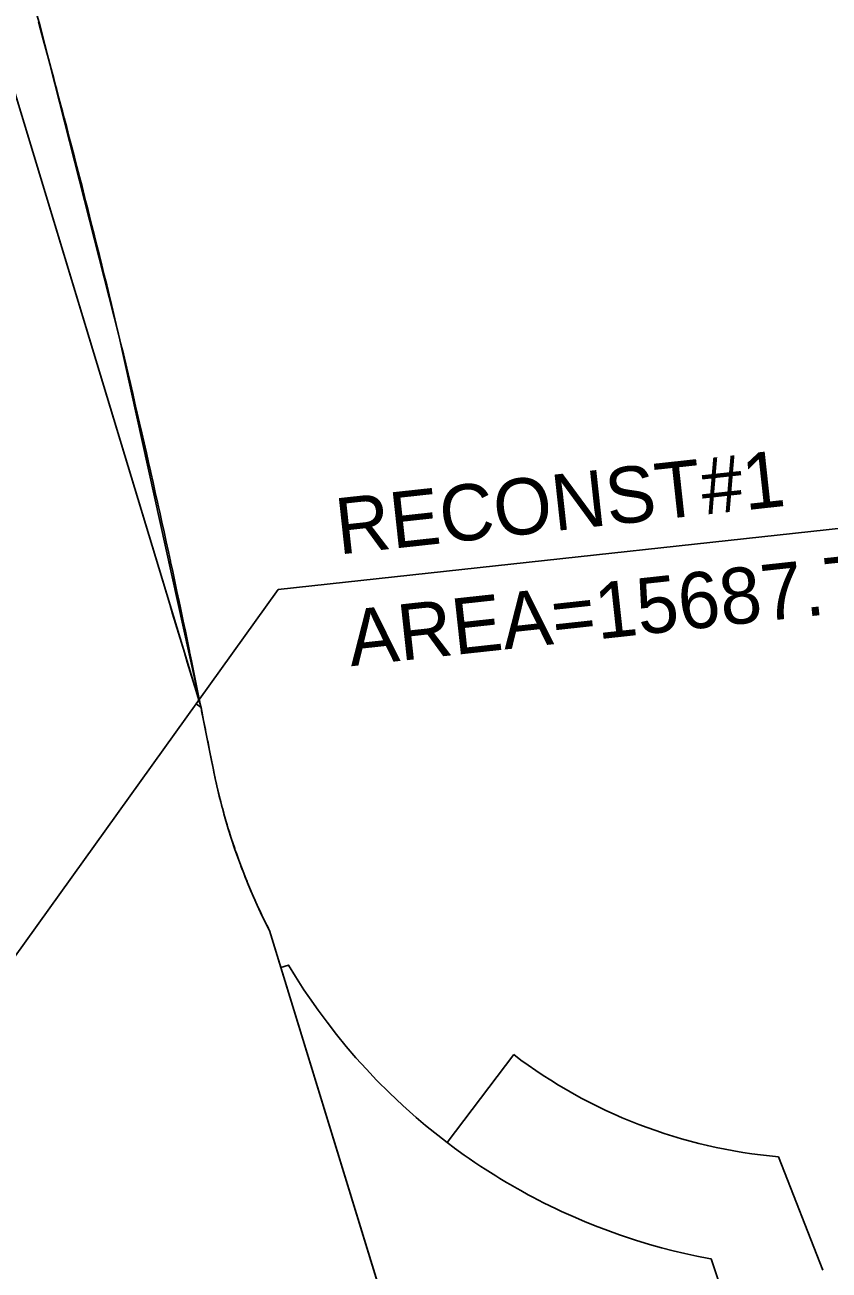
# Model space of a CAD drawing. Extents: x 1509538 to 1510847, y 401283 to 402022.
# Drawn here: x 1509788.8 to 1509828.9, y 401687.8 to 401749.8 of the extents above; entities that cross this region are included whole.
import ezdxf

# ---------------------------------------------------------------- set-up
doc = ezdxf.new("R2010")
doc.units = 0
for name, color, linetype in [('LAWE_P_T', 7, 'Continuous'), ('Level 2', 7, 'Continuous'), ('Level 3', 7, 'Continuous'), ('Level 5', 7, 'Continuous'), ('Level 8', 7, 'Continuous')]:
    doc.layers.add(name, color=color, linetype=linetype)

msp = doc.modelspace()

# ---------------------------------------------------------------- linework, layer by layer
at = {"layer": 'LAWE_P_T'}
msp.add_lwpolyline([(1509787.163, 401701.771), (1509801.464, 401721.693), (1509837.165, 401725.585)], dxfattribs=at)
at = {"layer": 'Level 2'}
for p, q in [((1509796.641, 401719.03), (1509796.494, 401719.512)), ((1509797.079, 401717.584), (1509796.933, 401718.066)), ((1509797.225, 401717.102), (1509797.079, 401717.584)), ((1509797.368, 401715.987), (1509797.505, 401716.178)), ((1509812.832, 401666.242), (1509801.026, 401704.701)), ((1509801.593, 401702.854), (1509801.026, 401704.701)), ((1509812.832, 401666.242), (1509801.593, 401702.854))]:
    msp.add_line(p, q, dxfattribs=at)
for points in [[(1509797.617, 401715.809), (1509783.046, 401763.871), (1509766.293, 401811.158), (1509745.325, 401858.521), (1509715.312, 401901.724)], [(1509796.056, 401720.959), (1509783.046, 401763.871), (1509766.293, 401811.158), (1509745.325, 401858.521)], [(1509796.494, 401719.512), (1509796.348, 401719.994), (1509796.202, 401720.476), (1509796.056, 401720.959)], [(1509796.933, 401718.066), (1509796.787, 401718.548), (1509796.641, 401719.03)], [(1509797.505, 401716.178), (1509797.371, 401716.621), (1509797.225, 401717.102)], [(1509797.617, 401715.809), (1509797.368, 401715.987)], [(1509801.026, 401704.701), (1509800.978, 401704.795), (1509800.94, 401704.87), (1509800.854, 401705.041), (1509800.804, 401705.142), (1509800.672, 401705.414), (1509800.652, 401705.457), (1509800.542, 401705.688), (1509800.509, 401705.759), (1509800.456, 401705.875), (1509800.415, 401705.964), (1509800.351, 401706.105), (1509800.291, 401706.24), (1509800.267, 401706.293), (1509800.169, 401706.518), (1509800.123, 401706.624), (1509800.086, 401706.713), (1509800.075, 401706.738), (1509800.05, 401706.797), (1509799.934, 401707.077), (1509799.911, 401707.133), (1509799.82, 401707.358), (1509799.743, 401707.555), (1509799.71, 401707.64), (1509799.674, 401707.732), (1509799.602, 401707.923), (1509799.581, 401707.978), (1509799.497, 401708.208), (1509799.427, 401708.402), (1509799.394, 401708.493), (1509799.308, 401708.739), (1509799.295, 401708.779), (1509799.279, 401708.826), (1509799.198, 401709.067), (1509799.137, 401709.252), (1509799.104, 401709.355), (1509799.013, 401709.644), (1509799.002, 401709.679), (1509798.977, 401709.758), (1509798.924, 401709.934), (1509798.914, 401709.969), (1509798.873, 401710.108), (1509798.839, 401710.225), (1509798.756, 401710.516), (1509798.751, 401710.537), (1509798.682, 401710.788), (1509798.677, 401710.809), (1509798.638, 401710.956), (1509798.635, 401710.967), (1509798.6, 401711.102), (1509798.526, 401711.396), (1509798.525, 401711.399), (1509798.454, 401711.691), (1509798.422, 401711.828), (1509798.422, 401711.831), (1509798.386, 401711.986), (1509798.324, 401712.265), (1509798.321, 401712.282), (1509798.258, 401712.579), (1509798.234, 401712.7), (1509798.199, 401712.876), (1509798.141, 401713.172), (1509798.043, 401713.669), (1509797.965, 401714.066), (1509797.945, 401714.165), (1509797.847, 401714.661), (1509797.835, 401714.721), (1509797.748, 401715.157), (1509797.648, 401715.652), (1509797.633, 401715.731), (1509797.617, 401715.809)], [(1509801.026, 401704.701), (1509800.672, 401705.414), (1509800.415, 401705.964), (1509800.169, 401706.518), (1509799.934, 401707.077), (1509799.71, 401707.64), (1509799.497, 401708.208), (1509799.308, 401708.739), (1509799.137, 401709.252), (1509798.977, 401709.758), (1509798.756, 401710.516), (1509798.6, 401711.102), (1509798.454, 401711.691), (1509798.324, 401712.265), (1509798.199, 401712.876), (1509798.043, 401713.669), (1509797.945, 401714.165), (1509797.847, 401714.661), (1509797.748, 401715.157), (1509797.617, 401715.809)]]:
    msp.add_lwpolyline(points, dxfattribs=at)
at = {"layer": 'Level 3'}
msp.add_line((1509797.617, 401715.809), (1509797.548, 401716.148), dxfattribs=at)
for points in [[(1509715.312, 401901.724), (1509745.325, 401858.521), (1509766.293, 401811.158), (1509783.046, 401763.871), (1509797.617, 401715.809)], [(1509797.548, 401716.148), (1509797.448, 401716.644), (1509797.347, 401717.139), (1509797.246, 401717.635), (1509797.144, 401718.13), (1509797.049, 401718.588), (1509797.041, 401718.625), (1509796.939, 401719.12), (1509796.835, 401719.615), (1509796.731, 401720.11), (1509796.627, 401720.605), (1509796.591, 401720.774), (1509796.522, 401721.1), (1509796.417, 401721.594), (1509796.311, 401722.089), (1509796.205, 401722.583), (1509796.098, 401723.078), (1509796.093, 401723.102), (1509795.991, 401723.572), (1509795.883, 401724.066), (1509795.775, 401724.56), (1509795.666, 401725.054), (1509795.557, 401725.547), (1509795.5, 401725.807), (1509795.448, 401726.041), (1509795.338, 401726.535), (1509795.227, 401727.028), (1509795.116, 401727.521), (1509795.097, 401727.607), (1509795.004, 401728.015), (1509794.892, 401728.508), (1509794.78, 401729.001), (1509794.667, 401729.494), (1509794.553, 401729.986), (1509794.439, 401730.479), (1509794.358, 401730.829), (1509794.325, 401730.972), (1509794.21, 401731.464), (1509794.094, 401731.956), (1509794.06, 401732.103), (1509793.978, 401732.449), (1509793.862, 401732.941), (1509793.745, 401733.433), (1509793.627, 401733.925), (1509793.51, 401734.416), (1509793.391, 401734.908), (1509793.272, 401735.399), (1509793.166, 401735.839), (1509793.153, 401735.891), (1509793.033, 401736.382), (1509792.983, 401736.589), (1509792.913, 401736.873), (1509792.792, 401737.364), (1509792.671, 401737.855), (1509792.549, 401738.346), (1509792.427, 401738.837), (1509792.304, 401739.327), (1509792.181, 401739.818), (1509792.057, 401740.308), (1509791.933, 401740.798), (1509791.924, 401740.837), (1509791.865, 401741.066), (1509791.809, 401741.288), (1509791.684, 401741.778), (1509791.558, 401742.268), (1509791.432, 401742.758), (1509791.305, 401743.248), (1509791.178, 401743.737), (1509791.051, 401744.226), (1509790.923, 401744.716), (1509790.794, 401745.205), (1509790.708, 401745.533), (1509790.666, 401745.694), (1509790.631, 401745.822), (1509790.536, 401746.183), (1509790.406, 401746.671), (1509790.367, 401746.818), (1509790.276, 401747.16), (1509790.145, 401747.648), (1509790.014, 401748.137), (1509789.882, 401748.625), (1509789.749, 401749.113), (1509789.617, 401749.601), (1509789.511, 401749.989)], [(1509812.832, 401666.242), (1509801.593, 401702.854), (1509801.98, 401702.973), (1509802.329, 401702.401), (1509802.75, 401701.745), (1509803.023, 401701.338), (1509803.452, 401700.727), (1509803.897, 401700.123), (1509804.366, 401699.518), (1509804.857, 401698.917), (1509805.338, 401698.356), (1509805.858, 401697.779), (1509806.366, 401697.242), (1509807.009, 401696.598), (1509807.67, 401695.974), (1509808.349, 401695.369), (1509808.808, 401694.98), (1509809.89, 401694.121), (1509810.241, 401693.858), (1509810.244, 401693.856), (1509810.248, 401693.853), (1509810.736, 401693.502), (1509810.985, 401693.33), (1509811.262, 401693.138), (1509811.563, 401692.939), (1509811.781, 401692.795), (1509812.307, 401692.462), (1509812.51, 401692.339), (1509812.84, 401692.139), (1509813.033, 401692.028), (1509813.379, 401691.828), (1509813.56, 401691.728), (1509813.924, 401691.527), (1509814.092, 401691.439), (1509814.475, 401691.237), (1509814.663, 401691.143), (1509815.032, 401690.958), (1509815.295, 401690.833), (1509815.595, 401690.691), (1509816.162, 401690.435), (1509816.735, 401690.191), (1509817.258, 401689.979), (1509817.894, 401689.736), (1509818.481, 401689.526), (1509819.071, 401689.329), (1509819.28, 401689.265), (1509819.98, 401689.05), (1509820.564, 401688.886), (1509821.151, 401688.734), (1509821.74, 401688.594), (1509822.333, 401688.465), (1509822.928, 401688.348), (1509823.042, 401688.328), (1509823.042, 401688.327), (1509828.278, 401672.51)]]:
    msp.add_lwpolyline(points, dxfattribs=at)
at = {"layer": 'Level 5'}
for p, q in [((1509789.583, 401749.833), (1509783.259, 401771.222)), ((1509793.533, 401734.281), (1509789.583, 401749.833)), ((1509797.622, 401715.782), (1509793.533, 401734.281)), ((1509801.026, 401704.701), (1509801.593, 401702.854)), ((1509801.593, 401702.854), (1509801.026, 401704.701)), ((1509801.593, 401702.854), (1509801.98, 401702.973)), ((1509801.98, 401702.973), (1509801.593, 401702.854)), ((1509801.98, 401702.973), (1509802.329, 401702.401)), ((1509802.329, 401702.401), (1509801.98, 401702.973)), ((1509802.329, 401702.401), (1509802.75, 401701.745)), ((1509802.75, 401701.745), (1509802.329, 401702.401)), ((1509802.75, 401701.745), (1509803.023, 401701.338)), ((1509803.023, 401701.338), (1509802.75, 401701.745)), ((1509803.023, 401701.338), (1509803.452, 401700.727)), ((1509803.452, 401700.727), (1509803.023, 401701.338)), ((1509803.452, 401700.727), (1509803.897, 401700.123)), ((1509803.897, 401700.123), (1509803.452, 401700.727)), ((1509803.897, 401700.123), (1509804.366, 401699.518)), ((1509804.366, 401699.518), (1509803.897, 401700.123)), ((1509804.366, 401699.518), (1509804.857, 401698.917)), ((1509804.857, 401698.917), (1509804.366, 401699.518)), ((1509804.857, 401698.917), (1509805.338, 401698.356)), ((1509805.338, 401698.356), (1509804.857, 401698.917)), ((1509805.338, 401698.356), (1509805.858, 401697.779)), ((1509805.858, 401697.779), (1509805.338, 401698.356)), ((1509813.205, 401698.509), (1509809.88, 401694.129)), ((1509805.858, 401697.779), (1509806.366, 401697.242)), ((1509806.366, 401697.242), (1509805.858, 401697.779)), ((1509806.366, 401697.242), (1509807.009, 401696.598)), ((1509807.009, 401696.598), (1509806.366, 401697.242)), ((1509807.009, 401696.598), (1509807.67, 401695.974)), ((1509807.67, 401695.974), (1509807.009, 401696.598)), ((1509807.67, 401695.974), (1509808.349, 401695.369)), ((1509808.349, 401695.369), (1509807.67, 401695.974)), ((1509808.349, 401695.369), (1509808.808, 401694.98)), ((1509808.808, 401694.98), (1509808.349, 401695.369)), ((1509808.808, 401694.98), (1509809.88, 401694.129)), ((1509809.88, 401694.129), (1509808.808, 401694.98)), ((1509828.611, 401687.769), (1509826.411, 401693.416)), ((1509828.592, 401687.821), (1509828.551, 401687.931))]:
    msp.add_line(p, q, dxfattribs=at)
for points in [[(1509797.612, 401715.825), (1509797.617, 401715.809)], [(1509797.617, 401715.809), (1509797.633, 401715.731), (1509797.648, 401715.652), (1509797.748, 401715.157), (1509797.835, 401714.721), (1509797.847, 401714.661), (1509797.945, 401714.165), (1509797.965, 401714.066), (1509798.043, 401713.669), (1509798.141, 401713.172), (1509798.199, 401712.876), (1509798.234, 401712.7), (1509798.258, 401712.579), (1509798.321, 401712.282), (1509798.324, 401712.265), (1509798.386, 401711.986), (1509798.422, 401711.831), (1509798.422, 401711.828), (1509798.454, 401711.691), (1509798.525, 401711.399), (1509798.526, 401711.396), (1509798.6, 401711.102), (1509798.635, 401710.967), (1509798.638, 401710.956), (1509798.677, 401710.809), (1509798.682, 401710.788), (1509798.751, 401710.537), (1509798.756, 401710.516), (1509798.839, 401710.225), (1509798.873, 401710.108), (1509798.914, 401709.969), (1509798.924, 401709.934), (1509798.977, 401709.758), (1509799.002, 401709.679), (1509799.013, 401709.644), (1509799.104, 401709.355), (1509799.137, 401709.252), (1509799.198, 401709.067), (1509799.279, 401708.826), (1509799.295, 401708.779), (1509799.308, 401708.739), (1509799.394, 401708.493), (1509799.427, 401708.402), (1509799.497, 401708.208), (1509799.581, 401707.978), (1509799.602, 401707.923), (1509799.674, 401707.732), (1509799.71, 401707.64), (1509799.743, 401707.555), (1509799.82, 401707.358), (1509799.911, 401707.133), (1509799.934, 401707.077), (1509800.05, 401706.797), (1509800.075, 401706.738), (1509800.086, 401706.713), (1509800.123, 401706.624), (1509800.169, 401706.518), (1509800.267, 401706.293), (1509800.291, 401706.24), (1509800.351, 401706.105), (1509800.415, 401705.964), (1509800.456, 401705.875), (1509800.509, 401705.759), (1509800.542, 401705.688), (1509800.652, 401705.457), (1509800.672, 401705.414), (1509800.804, 401705.142), (1509800.854, 401705.041), (1509800.94, 401704.87), (1509800.978, 401704.795), (1509801.026, 401704.701)], [(1509801.026, 401704.701), (1509800.978, 401704.795), (1509800.94, 401704.87), (1509800.854, 401705.041), (1509800.804, 401705.142), (1509800.672, 401705.414), (1509800.652, 401705.457), (1509800.542, 401705.688), (1509800.509, 401705.759), (1509800.456, 401705.875), (1509800.415, 401705.964), (1509800.351, 401706.105), (1509800.291, 401706.24), (1509800.267, 401706.293), (1509800.169, 401706.518), (1509800.123, 401706.624), (1509800.086, 401706.713), (1509800.075, 401706.738), (1509800.05, 401706.797), (1509799.934, 401707.077), (1509799.911, 401707.133), (1509799.82, 401707.358), (1509799.743, 401707.555), (1509799.71, 401707.64), (1509799.674, 401707.732), (1509799.602, 401707.923), (1509799.581, 401707.978), (1509799.497, 401708.208), (1509799.427, 401708.402), (1509799.394, 401708.493), (1509799.308, 401708.739), (1509799.295, 401708.779), (1509799.279, 401708.826), (1509799.198, 401709.067), (1509799.137, 401709.252), (1509799.104, 401709.355), (1509799.013, 401709.644), (1509799.002, 401709.679), (1509798.977, 401709.758), (1509798.924, 401709.934), (1509798.914, 401709.969), (1509798.873, 401710.108), (1509798.839, 401710.225), (1509798.756, 401710.516), (1509798.751, 401710.537), (1509798.682, 401710.788), (1509798.677, 401710.809), (1509798.638, 401710.956), (1509798.635, 401710.967), (1509798.6, 401711.102), (1509798.526, 401711.396), (1509798.525, 401711.399), (1509798.454, 401711.691), (1509798.422, 401711.828), (1509798.422, 401711.831), (1509798.386, 401711.986), (1509798.324, 401712.265), (1509798.321, 401712.282), (1509798.258, 401712.579), (1509798.234, 401712.7), (1509798.199, 401712.876), (1509798.141, 401713.172), (1509798.043, 401713.669), (1509797.965, 401714.066), (1509797.945, 401714.165), (1509797.847, 401714.661), (1509797.835, 401714.721), (1509797.748, 401715.157), (1509797.622, 401715.782)]]:
    msp.add_lwpolyline(points, dxfattribs=at)
msp.add_arc((1509828.623, 401718.82), 25.5, 232.79766, 265.02257, dxfattribs=at)
at = {"layer": 'Level 8'}
for p, q in [((1509796.494, 401719.512), (1509796.641, 401719.03)), ((1509796.933, 401718.066), (1509797.079, 401717.584)), ((1509797.079, 401717.584), (1509797.225, 401717.102)), ((1509797.505, 401716.178), (1509797.368, 401715.987)), ((1509797.368, 401715.987), (1509797.617, 401715.809)), ((1509801.026, 401704.701), (1509801.593, 401702.854)), ((1509801.593, 401702.854), (1509811.47, 401670.678))]:
    msp.add_line(p, q, dxfattribs=at)
for points in [[(1509745.325, 401858.521), (1509766.293, 401811.158), (1509783.046, 401763.871), (1509796.056, 401720.959)], [(1509796.056, 401720.959), (1509796.202, 401720.476), (1509796.348, 401719.994), (1509796.494, 401719.512)], [(1509796.641, 401719.03), (1509796.787, 401718.548), (1509796.933, 401718.066)], [(1509797.225, 401717.102), (1509797.371, 401716.621), (1509797.505, 401716.178)], [(1509797.617, 401715.809), (1509797.748, 401715.157), (1509797.847, 401714.661), (1509797.945, 401714.165), (1509798.043, 401713.669), (1509798.199, 401712.876), (1509798.324, 401712.265), (1509798.454, 401711.691), (1509798.6, 401711.102), (1509798.756, 401710.516), (1509798.977, 401709.758), (1509799.137, 401709.252), (1509799.308, 401708.739), (1509799.497, 401708.208), (1509799.71, 401707.64), (1509799.934, 401707.077), (1509800.169, 401706.518), (1509800.415, 401705.964), (1509800.672, 401705.414), (1509801.026, 401704.701)]]:
    msp.add_lwpolyline(points, dxfattribs=at)

# ---------------------------------------------------------------- texts
at = {"layer": 'LAWE_P_T'}
for s, height, p in [('RECONST#1', 2.8, (1509804.486, 401723.431)), ('AREA=15687.78 ft2', 2.79999, (1509805.093, 401717.864))]:
    msp.add_text(s, height=height, rotation=6.2219, dxfattribs=at).set_placement(p)

doc.saveas('drawing.dxf')
